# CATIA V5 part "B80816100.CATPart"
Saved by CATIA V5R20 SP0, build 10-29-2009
Part number: B80816100
Revision: 3
Definition: design
Nomenclature: B80816100
Source: made
Description: NOT SPECIFIED
Bounding box of the stored display mesh (mm): x -10 to 10, y -10 to 10, z 0 to 100
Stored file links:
  C:\Users\Raffaele\Desktop\3D X SITO CF\BOLEX\4-PILLAR REF 808\B80816100.CATPart
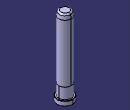
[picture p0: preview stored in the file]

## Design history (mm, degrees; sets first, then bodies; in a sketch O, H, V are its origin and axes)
Body1 "MANIFOLD_SOLID_BREP #450" (main body)
  Solid1: solid without history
